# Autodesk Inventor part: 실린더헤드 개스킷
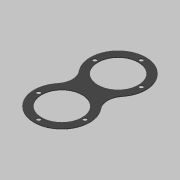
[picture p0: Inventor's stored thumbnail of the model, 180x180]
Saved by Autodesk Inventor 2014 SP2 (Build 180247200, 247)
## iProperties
Created: 2019-08
Part Number: 실린더헤드 개스킷
Material: 고무
Document SubType Name: Modeling
Designer: mduedu
Density: 0.93 g/cm^3
Appearance: 고무 - 검은색 - 버전 1.1
Mass: 5.11044 g
Surface Area: 119.346 cm^2
Volume: 5.49509 cm^3
Author: mduedu
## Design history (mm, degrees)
sketch "스케치1"
  geometry: L1 (0, 0)-(0, 85); C1 r 30.5 at (0, 85); C2 r 30.5 at (0, 0); A1 r 42 centre (0, 0) between (0, 42) and (-32.469, 26.642); A2 r 42 centre (0, 85) between (0, 43) and (32.469, 58.358); A3 r 25 centre (51.795, 42.5) between (32.469, 58.358) and (32.469, 26.642); A4 r 25 centre (-51.795, 42.5) between (-32.469, 26.642) and (-32.469, 58.358); A5 r 42 centre (0, 0) between (32.469, 26.642) and (0, 42); A6 r 42 centre (0, 0) between (-32.469, 26.642) and (32.469, 26.642); A7 r 42 centre (0, 85) between (-32.469, 58.358) and (0, 43); A8 r 42 centre (0, 85) between (32.469, 58.358) and (-32.469, 58.358); A9 r 25 centre (51.795, 42.5) between (32.469, 26.642) and (32.469, 58.358); A10 r 25 centre (-51.795, 42.5) between (-32.469, 58.358) and (-32.469, 26.642); 1 further point
  constraints: 20 point on circle, 12 centre point, 4 coincident, 4 tangent, 2 end point, 2 point on line, 1 vertical
  dimensions: "d1" = 84 diameter of A1; "d3" = 85 distance of L1.start L1.end; "d4" = 84 diameter of A2; "d5" = 50 diameter of A3; "d6" = 50 diameter of A4 (= d5); "d11" = 61 diameter of C1; "d12" = 61 diameter of C2
extrude "돌출2" new body sketch "스케치1" distance "d13" = 1; taper "d14" = 0 deg
sketch "스케치2"
  geometry: A1 r 35 centre (0, 0) between (-35, 0) and (0, 35); 2 further points
  constraints: 3 point on circle, 2 horizontal alignment, 1 centre point, 1 coincident, 1 vertical alignment
  dimensions: "d15" = 70 diameter of A1
hole "구멍1" sketch "스케치2" at (-35, 0), (0, 35), (35, 0) diameter "d16" = 6; stored, may be unused: countersink angle "d20" = 90 deg, drill point angle "d22" = 118 deg; dims "d17" = 6, "d18" = 4, "d19" = 2, "d21" = 8
node "작업 평면1"
mirror "대칭1"
node "솔리드2"
other parameters: "d23" = 42.5
